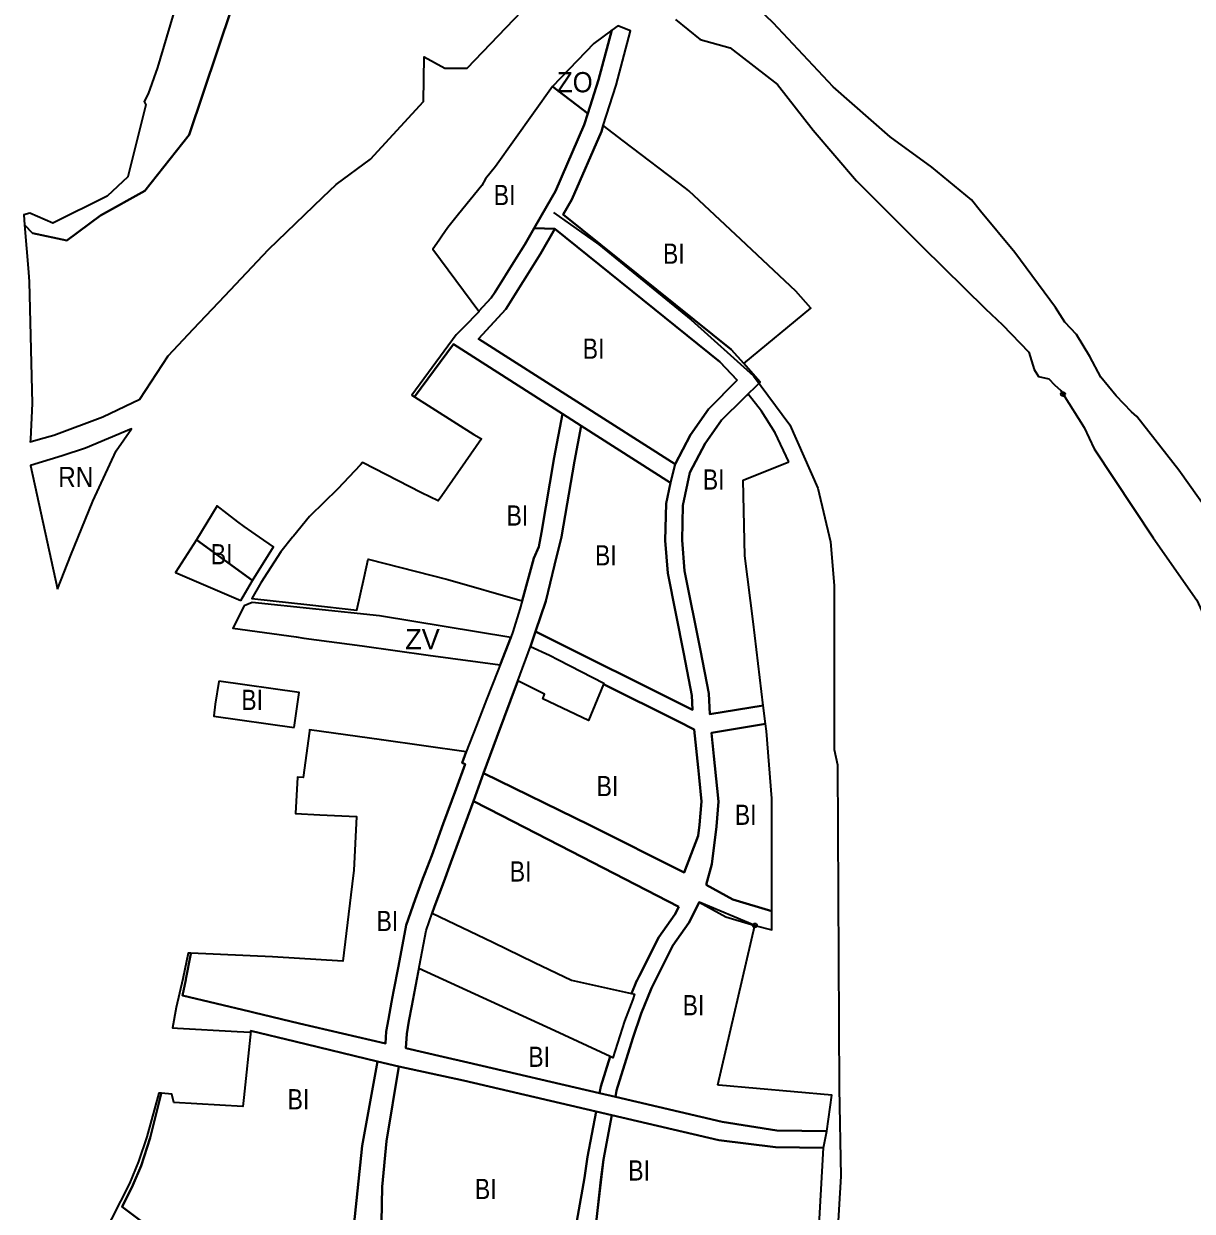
# Model space of a CAD drawing. Extents: x -650276 to -642489, y -1074311 to -1066720.
# Drawn here: x -645939 to -645245, y -1069933 to -1069228 of the extents above; entities that cross this region are included whole.
import ezdxf

# ---------------------------------------------------------------- set-up
doc = ezdxf.new("R2010")
doc.units = 0
doc.header["$LTSCALE"] = 4.8
doc.header["$PDMODE"] = 32
doc.header["$PDSIZE"] = 2.4
for name, color, linetype, lineweight in [('15', 7, 'Continuous', 35), ('2', 7, 'Continuous', 35), ('24', 7, 'Continuous', 35), ('40', 7, 'Continuous', 35), ('42', 7, 'Continuous', 35), ('48', 7, 'Continuous', 35), ('54', 7, 'Continuous', 35), ('7', 7, 'Continuous', 35)]:
    doc.layers.add(name, color=color, linetype=linetype, lineweight=lineweight)
doc.layers.add('62', color=7, linetype='Continuous')

msp = doc.modelspace()

# ---------------------------------------------------------------- linework, layer by layer
at = {"layer": '15'}
for p, q in [((-645552.336, -1069489.579), (-645555.072, -1069500.545)), ((-645638.203, -1069597.8), (-645635.153, -1069588.78))]:
    msp.add_line(p, q, dxfattribs=at)
for points in [[(-645589.844, -1069231.908), (-645597.738, -1069261.522), (-645604.114, -1069281.49)], [(-645594.94, -1069288.511), (-645587.298, -1069264.578), (-645578.713, -1069232.375), (-645586.39, -1069229.32), (-645589.844, -1069231.908)], [(-645604.114, -1069281.49), (-645606.256, -1069288.199), (-645623.307, -1069327.508), (-645628.492, -1069336.506), (-645635.995, -1069349.527), (-645623.694, -1069349.962)], [(-645618.766, -1069341.409), (-645613.576, -1069332.402), (-645596.062, -1069292.027), (-645594.94, -1069288.511)], [(-645511.585, -1069450.466), (-645501.878, -1069440.838), (-645511.464, -1069429.794), (-645519.097, -1069421.579), (-645618.766, -1069341.409)], [(-645669.039, -1069415.116), (-645652.804, -1069397.548), (-645632.191, -1069364.707), (-645623.694, -1069349.962), (-645635.995, -1069349.527)], [(-645635.995, -1069349.527), (-645641.511, -1069359.099), (-645647.304, -1069368.329), (-645659.41, -1069387.617)], [(-645623.694, -1069349.962), (-645525.761, -1069428.736), (-645515.509, -1069439.769)], [(-645659.41, -1069387.617), (-645661.477, -1069390.91), (-645668.722, -1069398.75)], [(-645668.722, -1069398.75), (-645668.61, -1069398.9), (-645678.06, -1069408.54)], [(-645678.06, -1069408.54), (-645682.28, -1069412.88), (-645696.45, -1069432.21), (-645708.48, -1069448.63), (-645707.04, -1069449.546)], [(-645619.119, -1069459.68), (-645608.04, -1069466.749), (-645555.072, -1069500.545), (-645552.336, -1069489.579), (-645669.039, -1069415.116)], [(-645707.04, -1069449.546), (-645683.883, -1069418.357), (-645619.119, -1069459.68)], [(-645515.509, -1069439.769), (-645532.534, -1069456.978), (-645543.158, -1069472.134), (-645552.336, -1069489.579), (-645555.072, -1069500.545)], [(-645531.753, -1069637.96), (-645532.36, -1069625.648), (-645537.354, -1069600.095), (-645546.74, -1069552.954), (-645548.207, -1069534.609), (-645547.654, -1069514.049), (-645543.548, -1069494.404), (-645534.584, -1069477.365), (-645524.812, -1069463.425), (-645511.585, -1069450.466)], [(-645555.072, -1069500.545), (-645557.65, -1069512.879), (-645558.241, -1069534.874), (-645556.685, -1069554.337), (-645547.188, -1069602.035), (-645542.336, -1069626.862), (-645541.922, -1069635.264), (-645635.153, -1069588.78), (-645638.203, -1069597.8)], [(-645638.203, -1069597.8), (-645626.95, -1069602.91), (-645621.56, -1069605.68), (-645594.58, -1069619.56), (-645594.818, -1069620.139), (-645550.62, -1069642.176), (-645541.064, -1069647.092)], [(-645530.797, -1069648.949), (-645498.61, -1069643.729), (-645500.137, -1069632.833), (-645531.753, -1069637.96)], [(-645541.064, -1069647.092), (-645538.744, -1069669.644), (-645538.15, -1069675.537)], [(-645533.953, -1069739.166), (-645530.534, -1069726.969), (-645527.824, -1069704.697), (-645526.643, -1069689.732), (-645528.772, -1069668.628), (-645530.797, -1069648.949)], [(-645538.15, -1069675.537), (-645536.707, -1069689.842), (-645537.8, -1069703.696), (-645538.579, -1069710.102), (-645546.93, -1069731.98), (-645602.91, -1069703.88), (-645665.961, -1069673.028), (-645671.999, -1069689.523), (-645655.45, -1069698.05), (-645614.28, -1069719.27), (-645550.184, -1069752.242)], [(-645539.126, -1069751.764), (-645538.096, -1069749.446), (-645522.277, -1069758.205), (-645504.976, -1069763.332), (-645495, -1069766), (-645495, -1069754.815), (-645518, -1069748), (-645533.953, -1069739.166)], [(-645587.785, -1069865.117), (-645587.052, -1069861.272), (-645577.497, -1069830.237), (-645572.56, -1069815.628), (-645566.341, -1069800.49), (-645553.635, -1069775.217), (-645544.108, -1069761.733), (-645539.126, -1069751.764)], [(-645550.184, -1069752.242), (-645552.437, -1069756.749), (-645561.956, -1069770.224), (-645573.652, -1069793.487)], [(-645573.652, -1069793.487), (-645575.153, -1069796.472), (-645578.134, -1069803.73)], [(-645578.134, -1069803.73), (-645576.34, -1069804.13), (-645577.52, -1069807.26), (-645582.31, -1069820.05), (-645589.23, -1069841.89), (-645590.964, -1069841.09)], [(-645726.542, -1069939.398), (-645726.131, -1069918.457), (-645723.668, -1069891.356), (-645716.277, -1069847.01), (-645729.006, -1069844.136), (-645738.039, -1069894.231), (-645742.967, -1069941.862)], [(-645590.964, -1069841.09), (-645596.458, -1069858.935), (-645597.216, -1069862.91), (-645587.785, -1069865.117)], [(-645833, -1069966), (-645880.431, -1069930.3), (-645874.219, -1069917.496), (-645869.262, -1069905.935), (-645863.95, -1069889.468), (-645857.289, -1069863.338), (-645857.204, -1069862.954), (-645858.78, -1069862.84), (-645865.78, -1069888.76), (-645870.89, -1069903.5), (-645876.15, -1069916.47), (-645892.09, -1069947.98)], [(-645601.753, -1069962.317), (-645598.491, -1069932.472), (-645596.463, -1069914.335), (-645594.866, -1069902.242), (-645589.84, -1069875.892), (-645599.271, -1069873.685), (-645604.424, -1069900.701), (-645606.07, -1069913.163), (-645614.072, -1069957.797)]]:
    msp.add_lwpolyline(points, dxfattribs=at)
msp.add_lwpolyline([(-645812.18, -1069826.3), (-645804.28, -1069826.76), (-645804.185, -1069825.84), (-645777.852, -1069832.241), (-645729.006, -1069844.136), (-645716.277, -1069847.01), (-645677.849, -1069855.3), (-645599.271, -1069873.685), (-645589.84, -1069875.892), (-645526.451, -1069890.745), (-645492.842, -1069895), (-645464.288, -1069895.362), (-645462.303, -1069885.376), (-645492, -1069885), (-645524.43, -1069879.921), (-645587.785, -1069865.117), (-645597.216, -1069862.91), (-645675.369, -1069844.625), (-645689.909, -1069841.272), (-645712.203, -1069836.131), (-645711.644, -1069827.736), (-645710.289, -1069820.217), (-645708.633, -1069811.027), (-645700.028, -1069766.286), (-645696.517, -1069756.039), (-645695.176, -1069752.125), (-645689.63, -1069737.38), (-645685.351, -1069726.002), (-645671.999, -1069689.523), (-645665.961, -1069673.028), (-645658.119, -1069651.601), (-645645.715, -1069618.085), (-645638.203, -1069597.8), (-645635.153, -1069588.78), (-645629.102, -1069570.857), (-645623.814, -1069549.548), (-645619.662, -1069532.642), (-645612.028, -1069487.724), (-645608.04, -1069466.749), (-645619.119, -1069459.68), (-645624.041, -1069485.561), (-645631.62, -1069530.161), (-645633.29, -1069538.7), (-645636.09, -1069545.31), (-645643.16, -1069570.6), (-645644.56, -1069575.61), (-645648.68, -1069589.06), (-645649.91, -1069592.39), (-645656.15, -1069608.71), (-645657.52, -1069612.2), (-645664.19, -1069629.24), (-645670.23, -1069644.67), (-645676.34, -1069660.28), (-645678.73, -1069666.78), (-645676.984, -1069667.634), (-645682.314, -1069682.197), (-645689.959, -1069703.082), (-645696.794, -1069721.756), (-645700.87, -1069732.593), (-645701.968, -1069735.514), (-645706.663, -1069747.998), (-645711.852, -1069763.14), (-645716.534, -1069787.483), (-645719.436, -1069802.573), (-645720.632, -1069808.792), (-645722.474, -1069819.017), (-645723.777, -1069826.243), (-645724.25, -1069833.353), (-645775.326, -1069821.576), (-645802.431, -1069814.987), (-645804.657, -1069814.455), (-645844.737, -1069804.875), (-645842.728, -1069795.578), (-645842.648, -1069795.17), (-645839.721, -1069780.247), (-645839.658, -1069779.835), (-645841.41, -1069779.76), (-645844.57, -1069795.07), (-645848.35, -1069812.09), (-645850.63, -1069824.09), (-645847.62, -1069824.26)], close=True, dxfattribs=at)
at = {"layer": '2'}
for p, q in [((-645526.643, -1069689.732), (-645527.824, -1069704.697)), ((-645701.968, -1069735.514), (-645700.87, -1069732.593))]:
    msp.add_line(p, q, dxfattribs=at)
for points in [[(-645628.492, -1069336.506), (-645623.307, -1069327.508), (-645606.256, -1069288.199), (-645604.114, -1069281.49), (-645625.11, -1069265.42), (-645658.9, -1069312.83), (-645664.89, -1069320.2), (-645667, -1069324.06), (-645680.8, -1069341.08), (-645687.22, -1069349), (-645690.81, -1069354.28), (-645692.38, -1069356.67), (-645696.19, -1069362.01), (-645668.722, -1069398.75)], [(-645594.94, -1069288.511), (-645596.062, -1069292.027), (-645613.576, -1069332.402), (-645618.766, -1069341.409), (-645519.097, -1069421.579)], [(-645519.097, -1069421.579), (-645511.464, -1069429.794), (-645471.738, -1069397.026), (-645480.72, -1069386.96), (-645513.41, -1069356.18), (-645544.26, -1069327.35), (-645546.19, -1069325.81), (-645583.13, -1069297.55), (-645594.94, -1069288.511)], [(-645647.304, -1069368.329), (-645641.511, -1069359.099), (-645635.995, -1069349.527), (-645628.492, -1069336.506)], [(-645623.694, -1069349.962), (-645632.191, -1069364.707), (-645652.804, -1069397.548), (-645669.039, -1069415.116), (-645552.336, -1069489.579)], [(-645515.509, -1069439.769), (-645525.761, -1069428.736), (-645623.694, -1069349.962)], [(-645668.722, -1069398.75), (-645661.477, -1069390.91), (-645659.41, -1069387.617), (-645647.304, -1069368.329)], [(-645552.336, -1069489.579), (-645543.158, -1069472.134), (-645532.534, -1069456.978), (-645515.509, -1069439.769)], [(-645511.585, -1069450.466), (-645524.812, -1069463.425), (-645534.584, -1069477.365), (-645543.548, -1069494.404), (-645547.654, -1069514.049), (-645548.207, -1069534.609)], [(-645484.783, -1069488.256), (-645493, -1069471), (-645501, -1069458), (-645508.994, -1069447.955), (-645511.585, -1069450.466)], [(-645608.04, -1069466.749), (-645612.028, -1069487.724), (-645619.662, -1069532.642), (-645623.814, -1069549.548), (-645629.102, -1069570.857), (-645635.153, -1069588.78), (-645541.922, -1069635.264)], [(-645541.922, -1069635.264), (-645542.336, -1069626.862), (-645547.188, -1069602.035), (-645556.685, -1069554.337), (-645558.241, -1069534.874), (-645557.65, -1069512.879), (-645555.072, -1069500.545), (-645608.04, -1069466.749)], [(-645500.137, -1069632.833), (-645506, -1069583), (-645511, -1069544), (-645512, -1069499), (-645484.783, -1069488.256)], [(-645548.207, -1069534.609), (-645546.74, -1069552.954), (-645537.354, -1069600.095)], [(-645537.354, -1069600.095), (-645532.36, -1069625.648), (-645531.753, -1069637.96), (-645500.137, -1069632.833)], [(-645823.082, -1069618.279), (-645823.13, -1069618.452), (-645825.295, -1069632.053), (-645826.133, -1069638.843), (-645826.151, -1069639.057), (-645778.45, -1069645.92)], [(-645778.45, -1069645.92), (-645775.46, -1069625.13), (-645823.082, -1069618.279)], [(-645645.715, -1069618.085), (-645658.119, -1069651.601), (-645665.961, -1069673.028), (-645602.91, -1069703.88), (-645546.93, -1069731.98), (-645538.579, -1069710.102)], [(-645538.15, -1069675.537), (-645538.744, -1069669.644), (-645541.064, -1069647.092), (-645550.62, -1069642.176), (-645594.818, -1069620.139), (-645603.7, -1069641.75), (-645630.93, -1069628.84), (-645629.78, -1069626.03), (-645645.715, -1069618.085)], [(-645700.87, -1069732.593), (-645696.794, -1069721.756), (-645689.959, -1069703.082), (-645682.314, -1069682.197), (-645676.984, -1069667.634), (-645678.73, -1069666.78), (-645676.34, -1069660.28), (-645726.57, -1069653.22), (-645769.264, -1069647.213), (-645769.36, -1069648), (-645773.02, -1069675.47), (-645776.45, -1069675.26), (-645777.62, -1069696.85), (-645763.24, -1069697.58), (-645741.43, -1069698.68), (-645743.01, -1069730.72), (-645743.36, -1069733.7), (-645749.48, -1069784.61), (-645791.2, -1069781.92), (-645839.658, -1069779.835)], [(-645495, -1069744), (-645495, -1069688), (-645498, -1069648), (-645498.61, -1069643.729), (-645530.793, -1069648.948), (-645530.757, -1069649.336)], [(-645530.757, -1069649.336), (-645528.772, -1069668.628), (-645526.643, -1069689.732)], [(-645538.579, -1069710.102), (-645537.8, -1069703.696), (-645536.707, -1069689.842), (-645538.15, -1069675.537)], [(-645550.184, -1069752.242), (-645614.28, -1069719.27), (-645655.45, -1069698.05), (-645671.999, -1069689.523), (-645685.351, -1069726.002), (-645689.63, -1069737.38), (-645695.176, -1069752.125), (-645696.517, -1069756.039), (-645660.57, -1069773.31)], [(-645527.824, -1069704.697), (-645530.534, -1069726.969), (-645533.953, -1069739.166)], [(-645716.534, -1069787.483), (-645711.852, -1069763.14), (-645706.663, -1069747.998), (-645701.968, -1069735.514)], [(-645533.953, -1069739.166), (-645518, -1069748), (-645495, -1069754.815), (-645495, -1069744)], [(-645574.28, -1069794.735), (-645573.652, -1069793.487), (-645561.956, -1069770.224), (-645552.437, -1069756.749), (-645550.184, -1069752.242)], [(-645504.976, -1069763.332), (-645538.096, -1069749.446), (-645539.126, -1069751.764), (-645544.108, -1069761.733)], [(-645577.497, -1069830.237), (-645587.052, -1069861.272), (-645587.785, -1069865.117), (-645524.43, -1069879.921), (-645492, -1069885), (-645462.303, -1069885.376), (-645459.312, -1069864.01), (-645526.374, -1069858.055), (-645527, -1069858), (-645504.976, -1069763.332)], [(-645544.108, -1069761.733), (-645553.635, -1069775.217), (-645566.341, -1069800.49), (-645572.56, -1069815.628), (-645577.497, -1069830.237)], [(-645660.57, -1069773.31), (-645635.79, -1069785.23), (-645613.84, -1069795.78), (-645578.134, -1069803.731), (-645576.185, -1069798.985)], [(-645839.658, -1069779.835), (-645839.721, -1069780.247), (-645842.648, -1069795.17)], [(-645722.474, -1069819.017), (-645720.632, -1069808.792), (-645719.436, -1069802.573), (-645716.534, -1069787.483)], [(-645590.964, -1069841.09), (-645623.75, -1069825.97), (-645704.355, -1069788.786), (-645708.633, -1069811.027), (-645710.289, -1069820.217), (-645711.644, -1069827.736), (-645712.203, -1069836.131)], [(-645842.648, -1069795.17), (-645842.728, -1069795.578), (-645844.737, -1069804.875), (-645804.657, -1069814.455)], [(-645576.185, -1069798.985), (-645575.153, -1069796.472), (-645574.28, -1069794.735)], [(-645804.657, -1069814.455), (-645802.431, -1069814.987), (-645775.326, -1069821.576), (-645724.25, -1069833.353)], [(-645724.25, -1069833.353), (-645723.777, -1069826.243), (-645722.474, -1069819.017)], [(-645712.203, -1069836.131), (-645689.909, -1069841.272), (-645675.369, -1069844.625), (-645597.216, -1069862.91)], [(-645597.216, -1069862.91), (-645596.458, -1069858.935), (-645590.964, -1069841.09)]]:
    msp.add_lwpolyline(points, dxfattribs=at)
for points in [[(-645778.754, -1069532.198), (-645779.376, -1069532.962), (-645786.388, -1069541.673), (-645798.102, -1069559.972), (-645803.513, -1069569.263), (-645769.04, -1069573), (-645741.14, -1069576.19), (-645736.8, -1069556.91), (-645734.5, -1069545.89), (-645687.29, -1069558.04), (-645643.16, -1069570.6), (-645636.09, -1069545.31), (-645633.29, -1069538.7), (-645631.62, -1069530.161), (-645624.041, -1069485.561), (-645619.119, -1069459.68), (-645683.883, -1069418.357), (-645707.04, -1069449.546), (-645671.75, -1069471.99), (-645667.31, -1069474.6), (-645690.84, -1069508.32), (-645692.87, -1069511.229), (-645702.82, -1069506.64), (-645737.897, -1069488.534), (-645738.986, -1069489.868), (-645752.715, -1069504.328), (-645768.995, -1069520.305), (-645769.369, -1069520.672)], [(-645803.07, -1069558.62), (-645790.62, -1069538.59), (-645799.07, -1069532.8), (-645808.1, -1069526.61), (-645811.75, -1069523.81), (-645824.05, -1069514.34), (-645836.44, -1069534.5)], [(-645810.08, -1069570.39), (-645803.07, -1069558.62), (-645836.44, -1069534.5), (-645848.78, -1069553.91)], [(-645806, -1069959), (-645768.424, -1069948.431), (-645742.967, -1069941.862), (-645738.039, -1069894.231), (-645729.006, -1069844.136), (-645777.852, -1069832.241), (-645804.185, -1069825.84), (-645808.28, -1069865.39), (-645808.84, -1069870.75), (-645849.79, -1069868.4), (-645850.92, -1069863.41), (-645857.204, -1069862.954), (-645857.289, -1069863.338), (-645863.95, -1069889.468), (-645869.262, -1069905.935), (-645874.219, -1069917.496), (-645880.431, -1069930.3), (-645833, -1069966)], [(-645606.07, -1069913.163), (-645604.424, -1069900.701), (-645599.271, -1069873.685), (-645677.849, -1069855.3), (-645716.277, -1069847.01), (-645723.668, -1069891.356), (-645726.131, -1069918.457), (-645726.542, -1069939.398), (-645699.889, -1069939.714), (-645670.325, -1069943.002), (-645625.979, -1069954.92), (-645614.072, -1069957.797)], [(-645589.84, -1069875.892), (-645594.866, -1069902.242), (-645598.491, -1069932.472), (-645601.753, -1069962.317), (-645547.4, -1069976.382), (-645490.814, -1069988.074), (-645469.701, -1069990.011), (-645469.701, -1069990.011), (-645464.288, -1069895.362), (-645492.842, -1069895), (-645526.451, -1069890.745)]]:
    msp.add_lwpolyline(points, close=True, dxfattribs=at)
msp.add_point((-645504.976, -1069763.332), dxfattribs=at)
at = {"layer": '24'}
for points in [[(-645230.1, -1069525.98), (-645253.4, -1069493.06), (-645278.31, -1069461.33), (-645281.4, -1069458.4), (-645290.5, -1069449.03), (-645299.61, -1069437.97), (-645306.16, -1069425.55), (-645314.14, -1069412.54), (-645321.1, -1069405.21), (-645326.59, -1069396.64), (-645350.63, -1069363.98), (-645371.12, -1069339.47), (-645376.38, -1069332.65), (-645400.07, -1069313.32), (-645424.8, -1069295.24), (-645458.45, -1069265.56), (-645494.13, -1069227.63), (-645515.89, -1069206.66), (-645534.25, -1069190.56), (-645543.43, -1069178.39)], [(-645552.2, -1069225.59), (-645537.44, -1069237.41), (-645519.59, -1069242.38), (-645491.63, -1069264.25), (-645470.44, -1069291.24), (-645444.62, -1069321.35), (-645405.7, -1069360.27), (-645368.13, -1069397.37), (-645358.04, -1069406.84), (-645342.49, -1069423.06), (-645339.31, -1069433.27), (-645336.66, -1069437.47), (-645330.57, -1069438.89), (-645327.2, -1069442.53), (-645323.36, -1069445.79), (-645322.13, -1069447.96)], [(-645322.13, -1069447.96), (-645309.62, -1069467.79), (-645303.57, -1069480.49), (-645268.57, -1069533.23), (-645242.75, -1069570.26), (-645230.42, -1069597.39), (-645227.27, -1069602.68), (-645225.7, -1069605.32), (-645214.76, -1069622.37), (-645198.41, -1069650.49), (-645185.17, -1069673.38), (-645179.12, -1069681.3), (-645170.3, -1069698.91), (-645158.43, -1069722.61), (-645153.44, -1069734.71), (-645140.27, -1069766.68), (-645123.84, -1069805.38), (-645108.74, -1069843.58), (-645094.42, -1069882.65), (-645083.31, -1069913.37), (-645071.53, -1069948.89), (-645063.96, -1069973.73), (-645063.23, -1069976.2), (-645062.57, -1069978.46)]]:
    msp.add_lwpolyline(points, dxfattribs=at)
msp.add_point((-645322.13, -1069447.96), dxfattribs=at)
at = {"layer": '40'}
msp.add_lwpolyline([(-645698.83, -1069602.85), (-645656.15, -1069608.71), (-645649.91, -1069592.39), (-645727.71, -1069579.61), (-645803.33, -1069571.62), (-645808.18, -1069573.7), (-645814.82, -1069586.81), (-645777.26, -1069592.07), (-645772.58, -1069592.73), (-645738.13, -1069597.46)], close=True, dxfattribs=at)
at = {"layer": '42'}
msp.add_lwpolyline([(-645604.114, -1069281.49), (-645597.738, -1069261.522), (-645589.844, -1069231.908), (-645600.55, -1069239.93), (-645625.11, -1069265.42)], close=True, dxfattribs=at)
at = {"layer": '48'}
msp.add_lwpolyline([(-645877.15, -1069319.06), (-645877.15, -1069319.06), (-645889.29, -1069330.52), (-645921.56, -1069346.6), (-645935.33, -1069340.64), (-645938.89, -1069341.56), (-645938.399, -1069347.452), (-645933.792, -1069352.53), (-645913.23, -1069356.892), (-645893.291, -1069341.938), (-645867.026, -1069327.317), (-645840.644, -1069294.052), (-645806.806, -1069193.112), (-645779.685, -1069122.296), (-645778.75, -1069108.98), (-645784.52, -1069075.66), (-645783.02, -1069061.84), (-645784.69, -1069060.74), (-645807.89, -1069094.51), (-645829.96, -1069154.65), (-645859.43, -1069254.08), (-645864.96, -1069269.78), (-645867.42, -1069274.21), (-645866.45, -1069276.32)], close=True, dxfattribs=at)
at = {"layer": '54'}
msp.add_lwpolyline([(-645624.473, -1069340.207), (-645597.606, -1069359.137), (-645542.894, -1069403.796), (-645505.738, -1069437.197), (-645484.202, -1069466.216), (-645467.655, -1069503.794), (-645460.072, -1069535.704), (-645458, -1069561.601), (-645458, -1069658.925), (-645456, -1069668), (-645455.002, -1069859.825), (-645453.95, -1069912.05), (-645458.804, -1069992.044), (-645455.073, -1070009.111)], dxfattribs=at)
at = {"layer": '7'}
msp.add_line((-645918.82, -1069563.81), (-645910.9, -1069543.64), dxfattribs=at)
for points in [[(-645806.806, -1069193.112), (-645840.644, -1069294.052), (-645867.026, -1069327.317), (-645893.291, -1069341.938), (-645913.23, -1069356.892), (-645933.792, -1069352.53), (-645938.399, -1069347.452), (-645936.046, -1069375.651), (-645935.58, -1069381.24), (-645933.97, -1069453.52), (-645934.8, -1069474.71), (-645935.05, -1069476.32), (-645928.99, -1069474.55), (-645921.13, -1069472.25), (-645892.03, -1069461.43), (-645869.91, -1069451.02), (-645853.28, -1069425.27), (-645838.17, -1069409.28), (-645819.62, -1069389.66), (-645793.63, -1069362.15), (-645761.411, -1069331.17), (-645753.58, -1069323.64), (-645733.1, -1069308.58), (-645701.62, -1069274.36), (-645701.33, -1069247.86), (-645689, -1069254.5), (-645675.82, -1069254.48), (-645643.34, -1069220.59)], [(-645910.9, -1069543.64), (-645897.92, -1069511.49), (-645884.01, -1069481.56), (-645875.02, -1069468.52), (-645902.19, -1069480.13), (-645916.13, -1069484.55), (-645934.97, -1069490.31), (-645918.82, -1069563.81)]]:
    msp.add_lwpolyline(points, dxfattribs=at)

# ---------------------------------------------------------------- texts
at = {"layer": '62'}
for s, width, p in [('ZO', 0.95, (-645622.428, -1069268.829)), ('BI', 0.85, (-645659.967, -1069335.79)), ('BI', 0.85, (-645559.537, -1069370.602)), ('BI', 0.85, (-645607.166, -1069426.988)), ('RN', 0.9, (-645918.459, -1069503.176)), ('BI', 0.85, (-645535.874, -1069504.638)), ('BI', 0.85, (-645652.376, -1069526.009)), ('BI', 0.85, (-645827.899, -1069548.998)), ('BI', 0.85, (-645599.874, -1069549.638)), ('BI', 0.85, (-645809.789, -1069635.433)), ('BI', 0.85, (-645598.928, -1069686.593)), ('BI', 0.85, (-645516.874, -1069703.638)), ('BI', 0.85, (-645650.447, -1069737.266)), ('BI', 0.85, (-645729.524, -1069766.68)), ('BI', 0.85, (-645547.874, -1069816.638)), ('BI', 0.85, (-645639.447, -1069847.266)), ('BI', 0.85, (-645782.319, -1069872.497)), ('BI', 0.85, (-645580.138, -1069914.734)), ('BI', 0.85, (-645671.138, -1069925.734))]:
    msp.add_text(s, height=12, dxfattribs=dict(at, width=width)).set_placement(p)
msp.add_text('ZV', height=12, dxfattribs=at).set_placement((-645712.51, -1069599.456))

doc.saveas('drawing.dxf')
